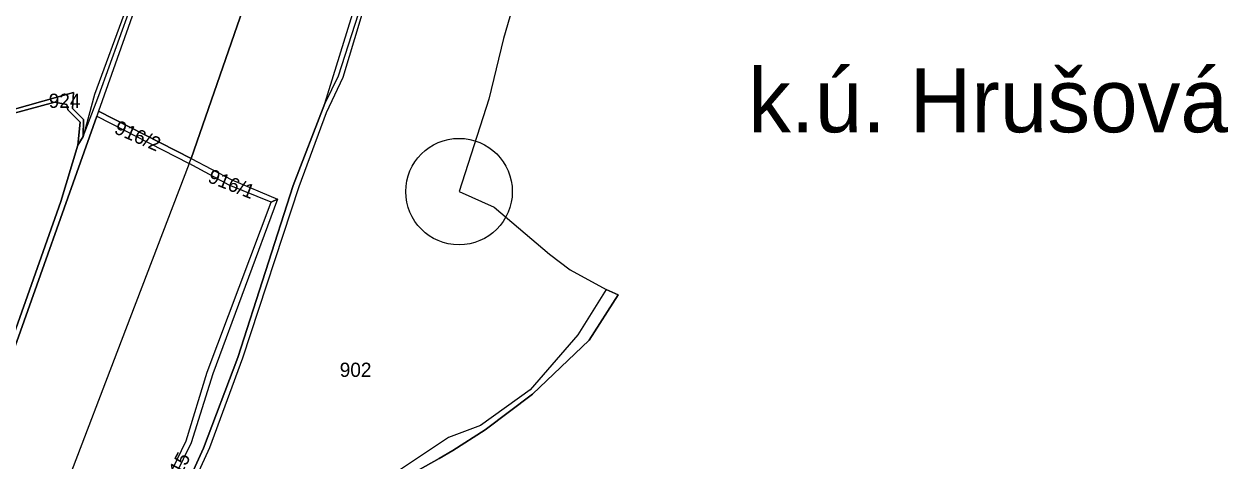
# Model space of a CAD drawing. Extents: x -623250 to -619626, y -1079612 to -1075424.
# Drawn here: x -621038 to -620191, y -1078207 to -1077899 of the extents above; entities that cross this region are included whole.
import ezdxf

# ---------------------------------------------------------------- set-up
doc = ezdxf.new("R2010")
doc.units = 0
for name, color, linetype in [('Bodové pole k revizi', 7, 'Continuous'), ('Hranice převzatá (KoPÚ Hrušová)', 7, 'Continuous'), ('Názvy katastrálních území', 7, 'Continuous'), ('Parcela nároku', 7, 'Continuous'), ('Parcelní číslo', 7, 'Continuous')]:
    doc.layers.add(name, color=color, linetype=linetype)

msp = doc.modelspace()

# ---------------------------------------------------------------- linework, layer by layer
at = {"layer": 'Bodové pole k revizi'}
msp.add_circle((-620731.88, -1078017.37), 37.5, dxfattribs=at)
at = {"layer": 'Hranice převzatá (KoPÚ Hrušová)'}
msp.add_lwpolyline([(-620687.13, -1077863.5), (-620700.69, -1077909.5), (-620711, -1077952.38), (-620731.88, -1078017.37), (-620707.25, -1078028.38), (-620668.19, -1078061.38), (-620653.75, -1078072.38), (-620628.25, -1078086.27), (-620619.75, -1078090), (-620640.25, -1078122), (-620680.14, -1078160.13), (-620713.4, -1078185.25), (-620736.29, -1078199.82), (-620745.89, -1078205.29), (-620765.16, -1078216.09)], dxfattribs=at)
at = {"layer": 'Parcela nároku'}
for points in [[(-621059.59, -1077869.55), (-621037.01, -1077787.76), (-621038.58, -1077777.48), (-621028.9, -1077762.35), (-621019.92, -1077734.84), (-621014.62, -1077676.88), (-620995.64, -1077661.49), (-620989.68, -1077648.78), (-620990.66, -1077642.5), (-620987.78, -1077631.69), (-620984.6, -1077613.84), (-620933.53, -1077631.69), (-620906.8, -1077639.72), (-620900.27, -1077645.54), (-620904.39, -1077686.35), (-620932.83, -1077787.71), (-620944.23, -1077816.78), (-620966.11, -1077888.43), (-620988.43, -1077949.08), (-620996.39, -1077978.66), (-620996.31, -1077966.5), (-621003.9, -1077958.75), (-621003.37, -1077947.59), (-621057.59, -1077962.86)], [(-621095.78, -1078240.75), (-621053.62, -1078141.34), (-621012.33, -1078024.41), (-621000.18, -1077984.59), (-620996.39, -1077978.66), (-620985.35, -1077949.77), (-620963.73, -1077889.14), (-620940.04, -1077817.61), (-620928.94, -1077788.67), (-620900.05, -1077686.58), (-620895.24, -1077667.22), (-620893.94, -1077652.95), (-620900.76, -1077638.04), (-620897.89, -1077637.25), (-620890.21, -1077651.83), (-620891.22, -1077667.97), (-620895.99, -1077686.91), (-620925.3, -1077789.59), (-620936.57, -1077819.5), (-620960.78, -1077890.46), (-620985.69, -1077960.76), (-620986.94, -1077964.3), (-621049.48, -1078140.79), (-621091.98, -1078240.75)], [(-620936.54, -1078261.78), (-620907.27, -1078197.5), (-620884.02, -1078134.35), (-620844.5, -1078013.8), (-620825.23, -1077961.55), (-620813.43, -1077936.71), (-620800.77, -1077894.78), (-620790.08, -1077856.13), (-620785.89, -1077829.76), (-620774.81, -1077795.6), (-620759.07, -1077753.6), (-620756.23, -1077730.51), (-620758.56, -1077729.89), (-620761.69, -1077752.96), (-620777.2, -1077794.38), (-620788.59, -1077829.88), (-620793.56, -1077855.59), (-620802.96, -1077892.36), (-620816.93, -1077935.96), (-620826.43, -1077955.22), (-620848.6, -1078013.01), (-620887.7, -1078134.29), (-620911.67, -1078198.04), (-620940.28, -1078260.6)], [(-620687.13, -1077863.5), (-620700.69, -1077909.5), (-620711, -1077952.38), (-620731.88, -1078017.37), (-620707.25, -1078028.38), (-620668.19, -1078061.38), (-620653.75, -1078072.38), (-620628.25, -1078086.27), (-620648.22, -1078118.19), (-620681.86, -1078157), (-620716.77, -1078182.21), (-620739.19, -1078190.59), (-620781.6, -1078218.67)], [(-620936.54, -1078261.78), (-620907.27, -1078197.5), (-620884.02, -1078134.35), (-620844.5, -1078013.8), (-620825.23, -1077961.55), (-620813.43, -1077936.71), (-620800.77, -1077894.78)], [(-621203.04, -1078268.81), (-621176.77, -1078204.28), (-621159.99, -1078167.02), (-621130.31, -1078080.39), (-621090.02, -1078000.84), (-621069.21, -1077973.87), (-621056.53, -1077965.29), (-621016.43, -1077954.35), (-621007.93, -1077955.94), (-621007.24, -1077959.89), (-620998.66, -1077968.4), (-621000.18, -1077984.59), (-621012.33, -1078024.41), (-621053.62, -1078141.34), (-621095.78, -1078240.75)], [(-621091.98, -1078240.75), (-621049.48, -1078140.79), (-620986.94, -1077964.3), (-620921.77, -1077997.49), (-620966.72, -1078114.79), (-621011.6, -1078232.04)], [(-620765.16, -1078216.09), (-620745.89, -1078205.29), (-620736.29, -1078199.82), (-620713.4, -1078185.25), (-620680.14, -1078160.13), (-620640.25, -1078122), (-620619.75, -1078090), (-620628.25, -1078086.27), (-620648.22, -1078118.19), (-620681.86, -1078157), (-620716.77, -1078182.21), (-620739.19, -1078190.59), (-620781.6, -1078218.67)]]:
    msp.add_lwpolyline(points, dxfattribs=at)
for points in [[(-620900.27, -1077645.54), (-620904.39, -1077686.35), (-620932.83, -1077787.71), (-620944.23, -1077816.78), (-620966.11, -1077888.43), (-620988.43, -1077949.08), (-620996.39, -1077978.66), (-620985.35, -1077949.77), (-620963.73, -1077889.14), (-620940.04, -1077817.61), (-620928.94, -1077788.67), (-620900.05, -1077686.58), (-620895.24, -1077667.22), (-620893.94, -1077652.95), (-620900.76, -1077638.04), (-620906.8, -1077639.72)], [(-620895.99, -1077686.91), (-620925.3, -1077789.59), (-620936.57, -1077819.5), (-620960.78, -1077890.46), (-620985.69, -1077960.76), (-620920.47, -1077994.08), (-620871.91, -1077853.59), (-620811.81, -1077671.44), (-620840.54, -1077647.21), (-620856.83, -1077642.24), (-620869.03, -1077640.15), (-620897.89, -1077637.25), (-620890.21, -1077651.83), (-620891.22, -1077667.97)], [(-620826.43, -1077955.22), (-620804.78, -1077885.64), (-620796.72, -1077854.91), (-620792.02, -1077829.18), (-620779.83, -1077792.13), (-620765.35, -1077749.61), (-620761.51, -1077729.06), (-620764.71, -1077713.2), (-620783.04, -1077694.81), (-620811.81, -1077671.44), (-620811.23, -1077665.26), (-620776.36, -1077697.62), (-620762.35, -1077712.35), (-620758.56, -1077729.89), (-620761.69, -1077752.96), (-620777.2, -1077794.38), (-620788.59, -1077829.88), (-620793.56, -1077855.59), (-620802.96, -1077892.36), (-620816.93, -1077935.96)], [(-620783.04, -1077694.81), (-620811.81, -1077671.44), (-620871.91, -1077853.59), (-620920.47, -1077994.08), (-620891.92, -1078009.19), (-620859.73, -1078022.67), (-620905.18, -1078145.77), (-620920.49, -1078194.28), (-620977.45, -1078310.76), (-621000.02, -1078348.69), (-621014.46, -1078377.63), (-621006.54, -1078400.13), (-620940.28, -1078260.6), (-620911.67, -1078198.04), (-620887.7, -1078134.29), (-620848.6, -1078013.01), (-620826.43, -1077955.22), (-620804.78, -1077885.64), (-620796.72, -1077854.91), (-620792.02, -1077829.18), (-620779.83, -1077792.13), (-620765.35, -1077749.61), (-620761.51, -1077729.06), (-620764.71, -1077713.2)], [(-621090.02, -1078000.84), (-621070.42, -1077970.83), (-621057.59, -1077962.86), (-621003.37, -1077947.59), (-621003.9, -1077958.75), (-620996.31, -1077966.5), (-620996.39, -1077978.66), (-621000.18, -1077984.59), (-620998.66, -1077968.4), (-621007.24, -1077959.89), (-621007.93, -1077955.94), (-621016.43, -1077954.35), (-621056.53, -1077965.29), (-621069.21, -1077973.87)], [(-620920.47, -1077994.08), (-620985.69, -1077960.76), (-620986.94, -1077964.3), (-620921.77, -1077997.49)], [(-620921.77, -1077997.49), (-620920.47, -1077994.08), (-620891.92, -1078009.19), (-620859.73, -1078022.67), (-620864.07, -1078024.91), (-620893.6, -1078012.73)], [(-621008.56, -1078404.36), (-621017.73, -1078377.42), (-621002.28, -1078346.64), (-620980.12, -1078309.1), (-620924.03, -1078192.83), (-620909.26, -1078144.65), (-620864.07, -1078024.91), (-620893.6, -1078012.73), (-620921.77, -1077997.49), (-620966.72, -1078114.79), (-621011.6, -1078232.04), (-621079.38, -1078380), (-621147.2, -1078528.01), (-621077.2, -1078550.1), (-621053.41, -1078498.33), (-621026.59, -1078434.43)], [(-620980.12, -1078309.1), (-620924.03, -1078192.83), (-620909.26, -1078144.65), (-620864.07, -1078024.91), (-620859.73, -1078022.67), (-620905.18, -1078145.77), (-620920.49, -1078194.28), (-620977.45, -1078310.76), (-621000.02, -1078348.69), (-621014.46, -1078377.63), (-621006.54, -1078400.13), (-621008.56, -1078404.36), (-621017.73, -1078377.42), (-621002.28, -1078346.64)]]:
    msp.add_lwpolyline(points, close=True, dxfattribs=at)

# ---------------------------------------------------------------- texts
at = {"layer": 'Názvy katastrálních území'}
msp.add_text('k.ú. Hrušová', height=45, dxfattribs=at).set_placement((-620528.35, -1077975.59))
at = {"layer": 'Parcelní číslo'}
for s, p in [('924', (-621020.74, -1077958.4)), ('902', (-620815.86, -1078147.87))]:
    msp.add_text(s, height=10, dxfattribs=at).set_placement(p)
for s, rotation, p in [('916/2', 336.52395, (-620975.38, -1077976)), ('916/1', 338.42493, (-620909.45, -1078010.45)), ('915', 62.02467, (-620931.1, -1078224.21))]:
    msp.add_text(s, height=10, rotation=rotation, dxfattribs=at).set_placement(p)

doc.saveas('drawing.dxf')
